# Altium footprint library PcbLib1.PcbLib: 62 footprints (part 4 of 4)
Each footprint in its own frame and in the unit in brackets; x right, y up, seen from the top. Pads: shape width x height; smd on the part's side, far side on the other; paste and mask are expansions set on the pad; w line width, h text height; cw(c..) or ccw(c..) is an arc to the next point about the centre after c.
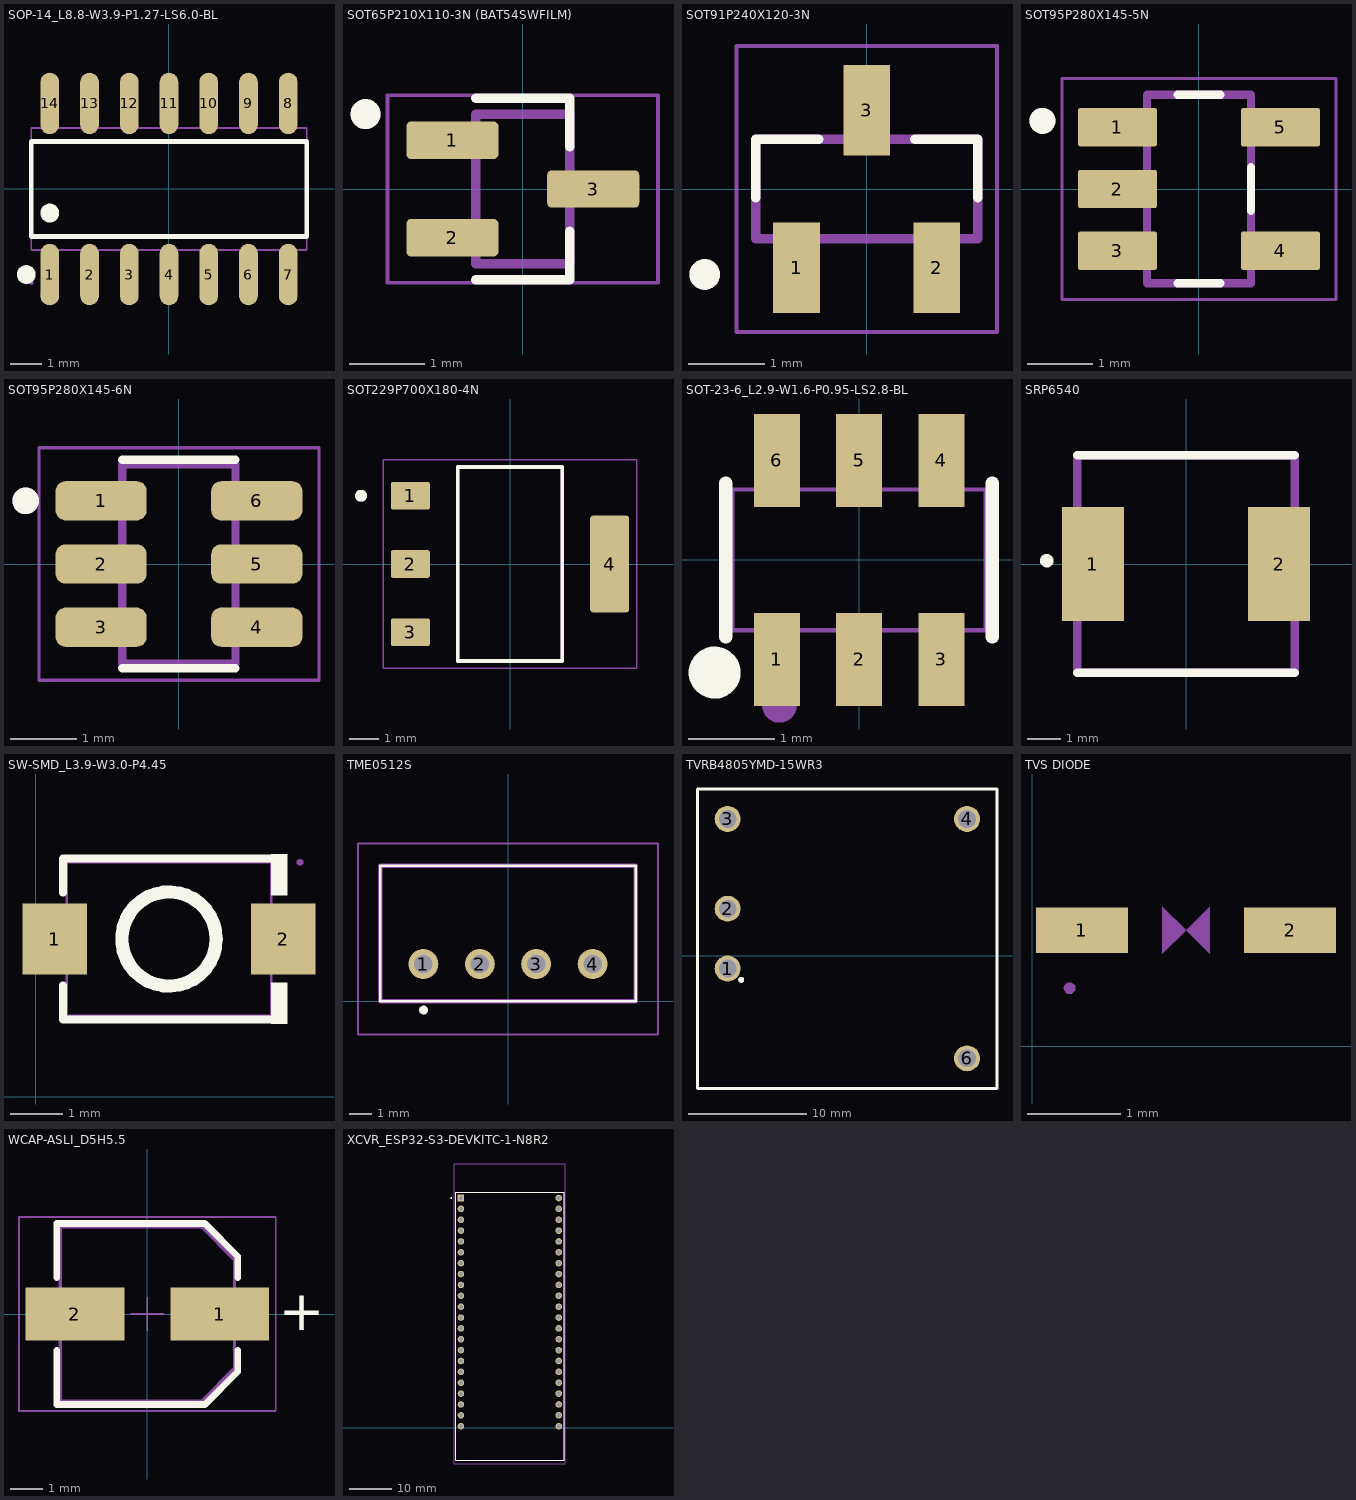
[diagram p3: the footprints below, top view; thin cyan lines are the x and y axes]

## SOP-14_L8.8-W3.9-P1.27-LS6.0-BL [mm]
pads (14):
  oval 0.595x1.968 smd: 1(-3.81,-2.734) 2(-2.54,-2.734) 3(-1.27,-2.734) 4(0,-2.734) 5(1.27,-2.734) 6(2.54,-2.734) 7(3.81,-2.734) 8(3.81,2.734) 9(2.54,2.734) 10(1.27,2.734) 11(0,2.734) 12(-1.27,2.734) 13(-2.54,2.734) 14(-3.81,2.734)
Top Overlay:
  circle w0.3: c-3.81,-0.769 r0.15
  circle w0.3: c-4.56,-2.734 r0.15
  lines w0.152: -4.401,-1.521 4.401,-1.521 4.401,1.521 -4.401,1.521 -4.401,-1.521
Mechanical 6:
  circle w0.3: c-3.81,-3.4 r0.15
Mechanical 15:
  drawing of 33 lines, arcs and shapes, not listed
3D body "CD4069UBM.stp": height 1.75, standoff 0, extent -4.319,-2.984 4.331,3.042

## SOT65P210X110-3N (BAT54SWFILM) [mm]
pads (3):
  rrect25% 1.23x0.5 smd: 1(-0.94,0.65) 2(-0.94,-0.65) 3(0.94,0)
Top Overlay:
  circle w0.2: c-2.1,1 r0.1
  lines w0.127: -0.625,-1.214 0.625,-1.214 0.625,-0.564 ; -0.625,1.214 0.625,1.214 0.625,0.564
Mechanical 13:
  circle w0.2: c-2.1,1 r0.1
  lines w0.127: -0.625,-1 -0.625,1 0.625,1 0.625,-1 -0.625,-1
Mechanical 15:
  lines w0.05: -1.805,-1.25 1.805,-1.25 1.805,1.25 -1.805,1.25 -1.805,-1.25
3D body "step_temp.STEP": height 1.1, standoff 0, extent -1.05,-1 1.05,1

## SOT91P240X120-3N [mm]
pads (3):
  rect 0.61x1.18 smd: 1(-0.915,-1.025) 2(0.915,-1.025) 3(0,1.025)
Top Overlay:
  circle w0.2: c-2.115,-1.115 r0.1
  lines w0.127: -1.45,-0.115 -1.45,0.65 -0.625,0.65 ; 0.625,0.65 1.45,0.65 1.45,-0.115
Mechanical 13:
  circle w0.2: c-2.115,-1.115 r0.1
  lines w0.127: -1.45,-0.65 1.45,-0.65 1.45,0.65 -1.45,0.65 -1.45,-0.65
Mechanical 15:
  lines w0.05: -1.7,-1.865 -1.7,1.865 1.7,1.865 1.7,-1.865 -1.7,-1.865
3D body "step_temp.STEP": height 1.15, standoff 0, extent -1.45,-0.946 1.45,1.454

## SOT95P280X145-5N [mm]
height 1.45
pads (5):
  rrect9% 1.21x0.59 smd: 1(-1.255,0.95) 2(-1.255,0) 3(-1.255,-0.95) 4(1.255,-0.95) 5(1.255,0.95)
Top Overlay:
  circle w0.2: c-2.41,1.05 r0.1
  lines w0.127: -0.33,-1.45 0.33,-1.45 ; -0.33,1.45 0.33,1.45 ; 0.8,-0.335 0.8,0.335
Mechanical 13:
  circle w0.2: c-2.41,1.05 r0.1
  lines w0.127: -0.8,-1.45 0.8,-1.45 0.8,1.45 -0.8,1.45 -0.8,-1.45
Mechanical 15:
  lines w0.05: -2.11,-1.7 -2.11,1.7 2.11,1.7 2.11,-1.7 -2.11,-1.7
3D body "step_temp.STEP": height 1.45, standoff 0, extent -1.4,-1.45 1.4,1.45

## SOT95P280X145-6N [mm]
height 1.45
pads (6):
  rrect50% 1.37x0.59 smd: 1(-1.17,0.95) 2(-1.17,0) 3(-1.17,-0.95) 4(1.17,-0.95) 5(1.17,0) 6(1.17,0.95)
Top Overlay:
  circle w0.2: c-2.305,0.95 r0.1
  lines w0.127: -0.85,-1.565 0.85,-1.565 ; -0.85,1.565 0.85,1.565
Mechanical 13:
  circle w0.2: c-2.305,0.95 r0.1
  lines w0.127: -0.85,-1.5 -0.85,1.5 0.85,1.5 0.85,-1.5 -0.85,-1.5
Mechanical 15:
  lines w0.05: -2.105,-1.75 -2.105,1.75 2.105,1.75 2.105,-1.75 -2.105,-1.75
3D body "step_temp.STEP": height 1.45, standoff 0, extent -1.4,-1.45 1.4,1.45

## SOT229P700X180-4N [mm]
height 1.8
pads (4):
  rrect15% 1.31x0.93 smd: 1(-3.345,2.29) 2(-3.345,0) 3(-3.345,-2.29)
  rrect15% 1.31x3.24 smd: 4(3.345,0)
Top Overlay:
  circle w0.2: c-5,2.29 r0.1
  lines w0.127: -1.753,-3.253 -1.753,3.253 1.753,3.253 1.753,-3.253 -1.753,-3.253
Mechanical 13:
  circle w0.2: c-5,2.29 r0.1
  lines w0.127: -1.753,-3.253 -1.753,3.253 1.753,3.253 1.753,-3.253 -1.753,-3.253
Mechanical 15:
  lines w0.05: -4.25,-3.502 4.25,-3.502 4.25,3.502 -4.25,3.502 -4.25,-3.502
3D body "step_temp.STEP": height 1.8, standoff 0, extent -3.626,-3.251 3.372,3.251

## SOT-23-6_L2.9-W1.6-P0.95-LS2.8-BL [mm]
pads (6):
  rect 0.532x1.072 smd: 1(-0.95,-1.149) 2(0,-1.149) 3(0.95,-1.149) 4(0.95,1.149) 5(0,1.149) 6(-0.95,1.149)
Top Overlay:
  circle w0.3: c-1.668,-1.301 r0.15
  lines w0.152: -1.539,-0.889 -1.539,0.889 ; 1.539,-0.889 1.539,0.889
Mechanical 6:
  circle w0.2: c-0.92,-1.68 r0.1
Mechanical 15:
  region: -1.165,0.935 -0.735,0.935 -0.735,0.803 -1.165,0.803
  region: -1.165,0.925 -0.735,0.925 -0.735,1.4 -1.165,1.4
  region: -0.215,0.935 0.215,0.935 0.215,0.803 -0.215,0.803
  region: -0.215,0.925 0.215,0.925 0.215,1.4 -0.215,1.4
  region: 0.735,0.935 1.165,0.935 1.165,0.803 0.735,0.803
  region: 0.735,0.925 1.165,0.925 1.165,1.4 0.735,1.4
  region: 0.735,-0.803 1.165,-0.803 1.165,-0.935 0.735,-0.935
  region: 0.735,-0.925 1.165,-0.925 1.165,-1.4 0.735,-1.4
  region: -0.215,-0.803 0.215,-0.803 0.215,-0.935 -0.215,-0.935
  region: -0.215,-0.925 0.215,-0.925 0.215,-1.4 -0.215,-1.4
  region: -1.165,-0.803 -0.735,-0.803 -0.735,-0.935 -1.165,-0.935
  region: -1.165,-0.925 -0.735,-0.925 -0.735,-1.4 -1.165,-1.4
  region: -1.403,-1.4 -1.403,-1.425 -1.438,-1.46 -1.488,-1.46 -1.523,-1.425 -1.523,-1.4 -1.523,-1.375 -1.488,-1.34 -1.438,-1.34 -1.403,-1.375
  lines w0.051: -1.463,-0.813 -1.463,0.813 1.463,0.813 1.463,-0.813 -1.463,-0.813

## SRP6540 [mm]
pads (2):
  rect 1.85x3.4 smd: 1(-2.775,0) 2(2.775,0)
Top Overlay:
  circle w0.254: c-4.154,0.099 r0.075
  lines w0.254: -3.25,-3.25 3.25,-3.25 ; -3.25,3.25 3.25,3.25
Mechanical 13:
  lines w0.254: -3.25,-3.25 -3.25,3.25 3.25,3.25 3.25,-3.25 -3.25,-3.25
3D body "SRP6540-100M.stp": height 3.99, standoff 0, extent -3.594,-3.251 3.594,3.251

## SW-SMD_L3.9-W3.0-P4.45 [mm]
pads (2):
  rect 1.23x1.36 smd: 1(0.361,3.014) 2(4.731,3.014)
Top Overlay:
  circle w0.254: c2.546,3.014 r0.9
  region: 4.496,1.397 4.496,2.182 4.801,2.182 4.801,1.397
  region: 4.496,4.632 4.496,3.847 4.801,3.847 4.801,4.632
  lines w0.152: 0.52,2.131 0.52,1.473 4.572,1.473 ; 0.52,3.898 0.52,4.556 4.572,4.556
Mechanical 15:
  region: 5.106,4.479 5.106,4.455 5.071,4.419 5.021,4.419 4.986,4.455 4.986,4.479 4.986,4.504 5.021,4.539 5.071,4.539 5.106,4.504
  region: 5.046,3.664 5.046,2.364 4.146,2.364 4.146,3.664
  region: 0.046,3.664 0.046,2.364 0.946,2.364 0.946,3.664
  lines w0.051: 0.596,1.549 4.496,1.549 4.496,4.479 0.596,4.479 0.596,1.549

## TME0512S [mm]
pads (4):
  round 1.349 hole 0.83: 1(-3.81,1.675) 2(-1.27,1.675) 3(1.27,1.675) 4(3.81,1.675)
Top Overlay:
  lines w0.1: -5.75,0 5.75,0 5.75,6.1 -5.75,6.1 -5.75,0
  lines w0.2: -3.9,-0.4 cw(c-3.8,-0.4) -3.7,-0.4 cw(c-3.8,-0.4) -3.9,-0.4
Mechanical 13:
  lines w0.2: -5.75,0 5.75,0 5.75,6.1 -5.75,6.1 -5.75,0
Mechanical 15:
  lines w0.1: -6.75,-1.5 6.75,-1.5 6.75,7.1 -6.75,7.1 -6.75,-1.5
3D body "TME0505S.stp": height 9.95, standoff -3.15, extent -5.66,-0.12 5.74,5.88

## TVRB4805YMD-15WR3 [mm]
pads (5):
  round 2.2 hole 1.5 paste-2539.97 mask+0.05: 1(15.554,-1.083) 2(15.554,3.997) 3(15.554,11.617) 4(35.874,11.617) 6(35.874,-8.703)
Top Overlay:
  circle w0.254: c16.704,-2.033 r0.127
  lines w0.254: 13.014,-11.243 13.014,14.157 38.414,14.157 38.414,-11.243 13.014,-11.243
Mechanical 6:
  circle w0.254: c16.704,-2.033 r0.127
Mechanical 15:
  region: 13.074,-11.243 13.074,-11.218 13.039,-11.183 12.989,-11.183 12.954,-11.218 12.954,-11.243 12.954,-11.268 12.989,-11.303 13.039,-11.303 13.074,-11.268
  region: 16.054,3.997 16.053,4.096 15.976,4.278 15.836,4.417 15.653,4.493 15.455,4.493 15.272,4.417 15.132,4.278 15.055,4.096 15.054,3.997 15.055,3.898 15.132,3.716 15.272,3.577 15.455,3.501 15.653,3.501 15.836,3.577 15.976,3.716 16.053,3.898
  region: 36.374,11.617 36.373,11.716 36.296,11.898 36.156,12.037 35.973,12.113 35.775,12.113 35.592,12.037 35.452,11.898 35.375,11.716 35.374,11.617 35.375,11.518 35.452,11.336 35.592,11.197 35.775,11.121 35.973,11.121 36.156,11.197 36.296,11.336 36.373,11.518
  region: 36.374,-8.703 36.373,-8.604 36.296,-8.422 36.156,-8.283 35.973,-8.207 35.775,-8.207 35.592,-8.283 35.452,-8.422 35.375,-8.604 35.374,-8.703 35.375,-8.802 35.452,-8.984 35.592,-9.123 35.775,-9.199 35.973,-9.199 36.156,-9.123 36.296,-8.984 36.373,-8.802
  region: 16.054,11.617 16.053,11.716 15.976,11.898 15.836,12.037 15.653,12.113 15.455,12.113 15.272,12.037 15.132,11.898 15.055,11.716 15.054,11.617 15.055,11.518 15.132,11.336 15.272,11.197 15.455,11.121 15.653,11.121 15.836,11.197 15.976,11.336 16.053,11.518
  region: 16.054,-1.083 16.053,-0.984 15.976,-0.802 15.836,-0.663 15.653,-0.587 15.455,-0.587 15.272,-0.663 15.132,-0.802 15.055,-0.984 15.054,-1.083 15.055,-1.182 15.132,-1.364 15.272,-1.503 15.455,-1.579 15.653,-1.579 15.836,-1.503 15.976,-1.364 16.053,-1.182
  lines w0.051: 13.014,-11.243 13.014,14.157 38.414,14.157 38.414,-11.243 13.014,-11.243

## TVS DIODE [mm]
pads (2):
  rect 0.985x0.49 smd: 1(0.534,1.245) 2(2.769,1.245)
Mechanical 6:
  region: 1.398,1.499 1.398,0.991 1.652,1.245
  region: 1.906,0.991 1.906,1.499 1.652,1.245
Mechanical 15:
  region: 0.462,0.625 0.461,0.649 0.426,0.684 0.377,0.684 0.342,0.649 0.342,0.625 0.342,0.6 0.377,0.566 0.426,0.566 0.461,0.6
3D body "BAT60JFILM.STEP": height 1, standoff -0.17, extent 0.407,0.578 2.907,1.858

## WCAP-ASLI_D5H5.5 [mm] "Aluminium Electrolytic V-Chip SMT Capacitors, 5x5.5mm"
height 5.5
pads (2):
  rect 3x1.6 smd: 1(2.2,0) 2(-2.2,0)
Top Overlay:
  lines w0.2: -2.75,-1.1 -2.75,-2.75 1.75,-2.75 2.75,-1.75 2.75,-1.1 ; -2.75,1.1 -2.75,2.75 1.75,2.75 2.75,1.75 2.75,1.1
  text "+" at 4,-0.5 h1.22
Top Courtyard:
  lines w0.05: -0.5,0 0.5,0 ; 0,-0.5 0,0.5 ; -3.9,-2.95 -3.9,2.95 3.9,2.95 3.9,-2.95 -3.9,-2.95
Top 3D Body:
  lines w0.1: -2.65,-2.65 1.65,-2.65 2.65,-1.65 2.65,1.65 1.65,2.65 -2.65,2.65 -2.65,-2.65
Top Designator:
  text ".Designator" at -7.498,-0.5 h1.5
Top Component Outline:
  lines w0.1: -2.65,-2.65 1.65,-2.65 2.65,-1.65 2.65,1.65 1.65,2.65 -2.65,2.65 -2.65,-2.65
3D body "5x5.5x1.4.stp": height 5.5, standoff 0, extent -3,-2.65 3,2.65

## XCVR_ESP32-S3-DEVKITC-1-N8R2 [mm]
pads (44):
  rect 1.53x1.53 / inner round 1.53 / far side rect 1.53x1.53 hole 1.02: J1_1(38.862,53.719)
  round 1.53 hole 1.02: J1_2(38.862,51.179) J1_3(38.862,48.639) J1_4(38.862,46.099) J1_5(38.862,43.559) J1_6(38.862,41.019) J1_7(38.862,38.479) J1_8(38.862,35.939) J1_9(38.862,33.399) J1_10(38.862,30.859) J1_11(38.862,28.319) J1_12(38.862,25.779) J1_13(38.862,23.239) J1_14(38.862,20.699) J1_15(38.862,18.159) J1_16(38.862,15.619) J1_17(38.862,13.079) J1_18(38.862,10.539) J1_19(38.862,7.999) J1_20(38.862,5.459) J1_21(38.862,2.919) J1_22(38.862,0.379) J3_1(61.722,53.719) J3_2(61.722,51.179) J3_3(61.722,48.639) J3_4(61.722,46.099) J3_5(61.722,43.559) J3_6(61.722,41.019) J3_7(61.722,38.479) J3_8(61.722,35.939) J3_9(61.722,33.399) J3_10(61.722,30.859) J3_11(61.722,28.319) J3_12(61.722,25.779) J3_13(61.722,23.239) J3_14(61.722,20.699) J3_15(61.722,18.159) J3_16(61.722,15.619) J3_17(61.722,13.079) J3_18(61.722,10.539) J3_19(61.722,7.999) J3_20(61.722,5.459) J3_21(61.722,2.919) J3_22(61.722,0.379)
Top Overlay:
  circle w0.2: c36.576,53.721 r0.1
  lines w0.127: 37.592,-7.621 62.992,-7.621 62.992,55.119 37.592,55.119 37.592,-7.621
Mechanical 13:
  circle w0.2: c36.576,53.721 r0.1
  lines w0.127: 37.592,-7.621 62.992,-7.621 62.992,55.119 37.592,55.119 37.592,-7.621
Mechanical 15:
  lines w0.05: 37.342,-8.461 63.242,-8.461 63.242,61.669 37.342,61.669 37.342,-8.461
3D body "step_temp.STEP": height 7.39, standoff -6, extent 37.592,-8.211 62.992,61.429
